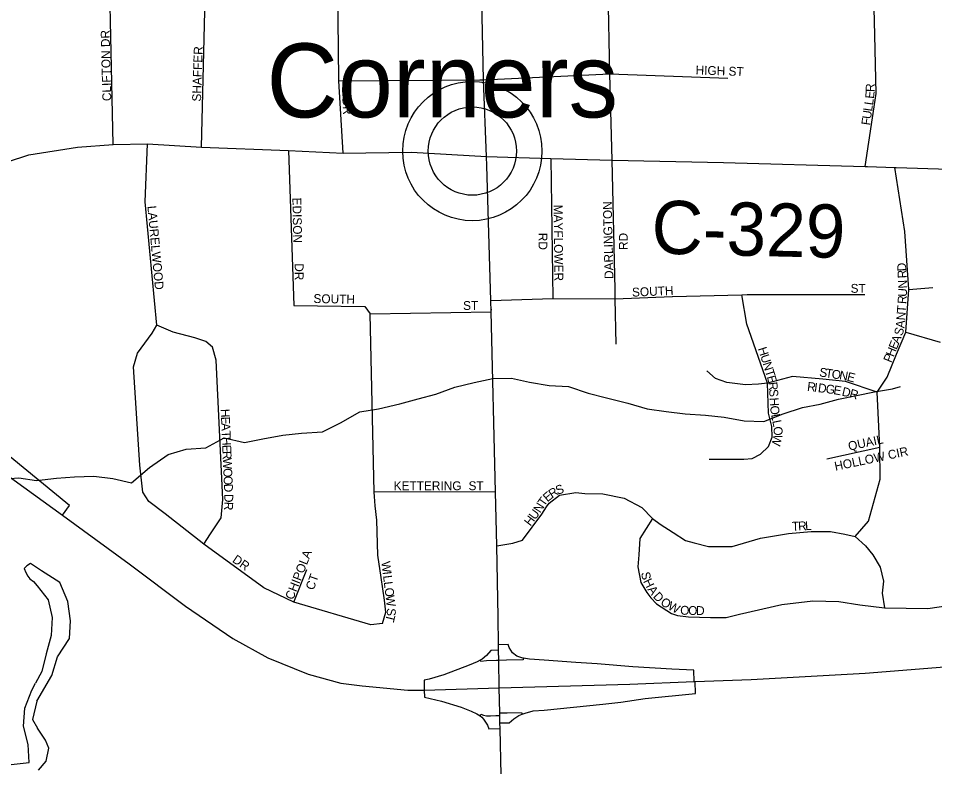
# Model space of a CAD drawing. Extents: x -37878.7 to -37844.7, y -19791.4 to -19769.4.
# Drawn here: x -37872 to -37871.021, y -19772.25 to -19771.451 of the extents above; entities that cross this region are included whole.
import ezdxf

# ---------------------------------------------------------------- set-up
doc = ezdxf.new("R2010")
doc.units = 0
for name, color, linetype in [('Default', 7, 'Continuous'), ('GM_X_County_Road', 7, 'Continuous'), ('GM_X_County_Road_Text', 7, 'Continuous'), ('GM_X_Interchange_Ramps', 7, 'Continuous'), ('GM_X_Major_River', 7, 'Continuous'), ('GM_X_Minor_River', 7, 'Continuous'), ('GM_X_State_Route', 7, 'Continuous'), ('GM_X_Township_Subdivision', 7, 'Continuous'), ('GM_X_Township_Subdivision_Text', 7, 'Continuous'), ('GM_X_Unincorporated', 7, 'Continuous'), ('GM_X_Unincorporated_Text', 7, 'Continuous')]:
    doc.layers.add(name, color=color, linetype=linetype)

msp = doc.modelspace()

# ---------------------------------------------------------------- linework, layer by layer
at = {"layer": 'Default'}
msp.add_line((-37871.51509, -19771.59241), (-37871.51509, -19771.59241), dxfattribs=at)
at = {"layer": 'GM_X_County_Road'}
for points in [[(-37872.01194, -19771.60377), (-37871.98912, -19771.59647), (-37871.93708, -19771.58825), (-37871.89901, -19771.58554), (-37871.86222, -19771.5846), (-37871.80471, -19771.58825), (-37871.71159, -19771.5919), (-37871.65316, -19771.59475), (-37871.57995, -19771.5934), (-37871.5, -19771.5981)], [(-37871.5, -19771.5981), (-37871.43129, -19771.60021), (-37871.36549, -19771.60206), (-37871.24669, -19771.60448), (-37871.09516, -19771.60885), (-37871.09272, -19771.60893), (-37871.0635, -19771.61001), (-37871.0623, -19771.61005), (-37871.00565, -19771.61165), (-37870.87873, -19771.6193), (-37870.79481, -19771.62682), (-37870.72767, -19771.63842), (-37870.70537, -19771.63741), (-37870.64056, -19771.65448), (-37870.56949, -19771.66605), (-37870.54222, -19771.67142), (-37870.49264, -19771.67596), (-37870.46113, -19771.67843), (-37870.24766, -19771.67679), (-37870.15647, -19771.6775), (-37870.10637, -19771.67103), (-37870.10594, -19771.67098)]]:
    msp.add_lwpolyline(points, dxfattribs=at)
at = {"layer": 'GM_X_Interchange_Ramps'}
for points in [[(-37871.95293, -19771.98122), (-37871.9456, -19771.97085), (-37872.07273, -19771.86712), (-37872.11453, -19771.83301), (-37872.28317, -19771.68716), (-37872.32336, -19771.65194), (-37872.49325, -19771.50307), (-37872.55567, -19771.44933), (-37872.57935, -19771.42714), (-37872.5973, -19771.40635), (-37872.61706, -19771.38265), (-37872.63797, -19771.35455), (-37872.67804, -19771.36574)], [(-37871.27805, -19772.15898), (-37871.27852, -19772.1469), (-37871.30204, -19772.14589), (-37871.34359, -19772.14315), (-37871.38156, -19772.13995), (-37871.40455, -19772.1385), (-37871.43829, -19772.13611), (-37871.45411, -19772.13522), (-37871.46054, -19772.13412), (-37871.46108, -19772.13402), (-37871.46742, -19772.13198), (-37871.4721, -19772.12823), (-37871.47574, -19772.12279), (-37871.47687, -19772.11959), (-37871.48711, -19772.11987)], [(-37871.48703, -19772.12549), (-37871.49542, -19772.12572), (-37871.49985, -19772.13099), (-37871.50469, -19772.13499), (-37871.50682, -19772.13619), (-37871.50996, -19772.13795), (-37871.51839, -19772.14132), (-37871.54558, -19772.15186), (-37871.56118, -19772.1565), (-37871.56665, -19772.15739), (-37871.56644, -19772.16804)], [(-37871.48685, -19772.13633), (-37871.4893, -19772.1364), (-37871.50006, -19772.13689), (-37871.50596, -19772.13773), (-37871.50682, -19772.13619)], [(-37871.46054, -19772.13412), (-37871.46085, -19772.13592), (-37871.47855, -19772.13611), (-37871.48685, -19772.13633)], [(-37871.48554, -19772.20324), (-37871.47569, -19772.203), (-37871.47077, -19772.19866), (-37871.4655, -19772.19508), (-37871.46195, -19772.19386), (-37871.45875, -19772.19276), (-37871.45011, -19772.19044), (-37871.43831, -19772.1896), (-37871.37572, -19772.18327), (-37871.35632, -19772.18096), (-37871.3304, -19772.17716), (-37871.27657, -19772.17162), (-37871.27707, -19772.15895)], [(-37871.56644, -19772.16804), (-37871.56631, -19772.17554), (-37871.54793, -19772.17993), (-37871.52686, -19772.18646), (-37871.51632, -19772.19068), (-37871.5102, -19772.19347), (-37871.50681, -19772.19548), (-37871.50485, -19772.19715), (-37871.50304, -19772.19911), (-37871.49903, -19772.20544), (-37871.49745, -19772.20941), (-37871.4854, -19772.20912)], [(-37871.50681, -19772.19548), (-37871.50597, -19772.19397), (-37871.50305, -19772.19507), (-37871.50007, -19772.19565), (-37871.49558, -19772.19557), (-37871.49005, -19772.19533), (-37871.48572, -19772.19524)], [(-37871.48578, -19772.19253), (-37871.47772, -19772.19234), (-37871.46255, -19772.19213), (-37871.46195, -19772.19386)]]:
    msp.add_lwpolyline(points, dxfattribs=at)
at = {"layer": 'GM_X_Major_River'}
for p, q in [((-37871.99116, -19772.03551), (-37871.99413, -19772.03814)), ((-37871.99413, -19772.03814), (-37871.99232, -19772.04234)), ((-37871.99232, -19772.04234), (-37871.99018, -19772.04637)), ((-37871.98721, -19772.03289), (-37871.99116, -19772.03551)), ((-37871.97995, -19772.03806), (-37871.98721, -19772.03289)), ((-37871.99018, -19772.04637), (-37871.98789, -19772.04934)), ((-37871.98789, -19772.04934), (-37871.98421, -19772.05201)), ((-37871.98421, -19772.05201), (-37871.98013, -19772.05691))]:
    msp.add_line(p, q, dxfattribs=at)
for points in [[(-37871.98068, -19772.18008), (-37871.9644, -19772.15246), (-37871.95859, -19772.13274), (-37871.94559, -19772.11305), (-37871.94472, -19772.09406), (-37871.94724, -19772.07354), (-37871.95582, -19772.05336), (-37871.97543, -19772.04074), (-37871.97995, -19772.03806)], [(-37871.98013, -19772.05691), (-37871.96843, -19772.07154), (-37871.96401, -19772.09055), (-37871.96526, -19772.10991), (-37871.97069, -19772.12926), (-37871.97535, -19772.14823), (-37871.98184, -19772.16074)], [(-37872.00807, -19772.24748), (-37871.98879, -19772.24555), (-37871.98995, -19772.22621), (-37871.9949, -19772.20658), (-37871.99341, -19772.18756), (-37871.98586, -19772.16804), (-37871.98184, -19772.16074)], [(-37871.98068, -19772.18008), (-37871.9852, -19772.19954), (-37871.9797, -19772.20891)], [(-37871.97877, -19772.25369), (-37871.97052, -19772.24397), (-37871.96754, -19772.23031), (-37871.97127, -19772.22156), (-37871.9797, -19772.20891)]]:
    msp.add_lwpolyline(points, dxfattribs=at)
at = {"layer": 'GM_X_Minor_River'}
for points in [[(-37871.98087, -19771.94423), (-37871.95965, -19771.94167), (-37871.94033, -19771.94024), (-37871.9195, -19771.93958), (-37871.89945, -19771.94196), (-37871.87941, -19771.94661), (-37871.86, -19771.93037), (-37871.84023, -19771.91641), (-37871.82088, -19771.9108), (-37871.80005, -19771.90938), (-37871.78029, -19771.89884), (-37871.75874, -19771.9035), (-37871.73903, -19771.89979), (-37871.7178, -19771.89572), (-37871.69772, -19771.89353), (-37871.67537, -19771.89212), (-37871.656, -19771.88272), (-37871.63548, -19771.87104), (-37871.61539, -19771.86772), (-37871.59264, -19771.86251), (-37871.57292, -19771.8569), (-37871.55396, -19771.85205), (-37871.53384, -19771.84455), (-37871.51299, -19771.83971), (-37871.49327, -19771.83525), (-37871.4732, -19771.83496), (-37871.45392, -19771.83923), (-37871.43312, -19771.84275), (-37871.4123, -19771.84399), (-37871.39114, -19771.85093), (-37871.37187, -19771.85596), (-37871.34881, -19771.86176), (-37871.3284, -19771.86756), (-37871.30797, -19771.87069), (-37871.28754, -19771.87307), (-37871.26597, -19771.87431), (-37871.24592, -19771.87669), (-37871.22474, -19771.88058), (-37871.20354, -19771.88107), (-37871.18305, -19771.87319), (-37871.16218, -19771.86645), (-37871.14322, -19771.86274), (-37871.12388, -19771.85751), (-37871.10455, -19771.85343), (-37871.08521, -19771.84972), (-37871.06588, -19771.8464), (-37871.05754, -19771.84377)], [(-37872.11221, -19771.98155), (-37872.09846, -19771.96354), (-37872.07821, -19771.95324), (-37872.05787, -19771.94787), (-37872.03828, -19771.94252), (-37872.01895, -19771.94286), (-37871.99966, -19771.94131), (-37871.98087, -19771.94423)]]:
    msp.add_lwpolyline(points, dxfattribs=at)
at = {"layer": 'GM_X_State_Route'}
for points in [[(-37871.4997, -19771.60813), (-37871.5, -19771.5981), (-37871.50303, -19771.51628), (-37871.50868, -19771.26212), (-37871.50889, -19771.23369), (-37871.51143, -19771.19794)], [(-37871.48915, -19771.99944), (-37871.49022, -19771.95652), (-37871.49513, -19771.76418), (-37871.49544, -19771.75192), (-37871.4997, -19771.60813)], [(-37872.0257, -19771.92896), (-37871.95293, -19771.98122), (-37871.88179, -19772.03336), (-37871.8216, -19772.07836), (-37871.77112, -19772.11308), (-37871.73362, -19772.13376), (-37871.69058, -19772.15118), (-37871.65576, -19772.16067), (-37871.63297, -19772.16353), (-37871.58392, -19772.16827), (-37871.56644, -19772.16804), (-37871.48639, -19772.16575)], [(-37871.48759, -19772.08976), (-37871.48879, -19772.01391), (-37871.48915, -19771.99944)], [(-37871.48639, -19772.16575), (-37871.48685, -19772.13633), (-37871.48703, -19772.12549), (-37871.48711, -19772.11987), (-37871.48759, -19772.08976)], [(-37871.21698, -19772.15663), (-37871.20426, -19772.15614), (-37871.09537, -19772.14992), (-37870.95701, -19772.13911)], [(-37871.48639, -19772.16575), (-37871.34662, -19772.16163), (-37871.27805, -19772.15898), (-37871.27707, -19772.15895), (-37871.21698, -19772.15663)], [(-37871.48426, -19772.25914), (-37871.4854, -19772.20912), (-37871.48554, -19772.20324), (-37871.48572, -19772.19524), (-37871.48578, -19772.19253), (-37871.48639, -19772.16575)]]:
    msp.add_lwpolyline(points, dxfattribs=at)
at = {"layer": 'GM_X_Township_Subdivision'}
for points in [[(-37871.89901, -19771.58554), (-37871.9049, -19771.30525), (-37871.90853, -19771.16537), (-37871.91106, -19771.02247), (-37871.91243, -19770.98276)], [(-37871.80471, -19771.58825), (-37871.79763, -19771.31186), (-37871.79517, -19771.23148)], [(-37871.65771, -19771.51587), (-37871.6591, -19771.38809), (-37871.66274, -19771.24545), (-37871.66071, -19771.2397)], [(-37871.09516, -19771.60885), (-37871.08339, -19771.53105), (-37871.08487, -19771.46857), (-37871.09051, -19771.23985)], [(-37871.36254, -19771.7401), (-37871.36549, -19771.60206), (-37871.36813, -19771.50983), (-37871.36993, -19771.41987), (-37871.37042, -19771.39232), (-37871.37042, -19771.38354), (-37871.3714, -19771.37525), (-37871.3714, -19771.36989), (-37871.3714, -19771.35794), (-37871.37154, -19771.34903)], [(-37871.50301, -19771.51628), (-37871.36813, -19771.50983), (-37871.24221, -19771.51454)], [(-37871.65316, -19771.59475), (-37871.65769, -19771.51731), (-37871.65771, -19771.51587)], [(-37871.65769, -19771.51731), (-37871.50714, -19771.5163), (-37871.50303, -19771.51628), (-37871.50301, -19771.51628)], [(-37871.61126, -19772.09697), (-37871.62368, -19772.09841), (-37871.7058, -19772.07406), (-37871.73779, -19772.05878), (-37871.80205, -19772.01216), (-37871.84331, -19771.98), (-37871.86098, -19771.96663), (-37871.86719, -19771.9566), (-37871.87053, -19771.92795), (-37871.87721, -19771.82291), (-37871.87292, -19771.80811), (-37871.85743, -19771.78685), (-37871.85239, -19771.77851), (-37871.86474, -19771.64678), (-37871.86222, -19771.5846)], [(-37871.71159, -19771.5919), (-37871.7058, -19771.7575)], [(-37871.43129, -19771.60021), (-37871.42914, -19771.74979)], [(-37871.10587, -19772.00399), (-37871.09155, -19771.98784), (-37871.07915, -19771.94271), (-37871.07964, -19771.90848), (-37871.08235, -19771.84992), (-37871.07167, -19771.8339), (-37871.06165, -19771.8092), (-37871.05164, -19771.78584), (-37871.0487, -19771.7402), (-37871.05297, -19771.67835), (-37871.0635, -19771.61001)], [(-37871.0487, -19771.7402), (-37871.02305, -19771.73803)], [(-37871.49544, -19771.75192), (-37871.42914, -19771.74979), (-37871.36232, -19771.7504), (-37871.30143, -19771.74781), (-37871.30128, -19771.7478)], [(-37871.36129, -19771.79877), (-37871.36232, -19771.7504), (-37871.36254, -19771.7401)], [(-37871.30128, -19771.7478), (-37871.22722, -19771.74578), (-37871.22132, -19771.74577)], [(-37871.26193, -19771.92136), (-37871.22485, -19771.92143), (-37871.21586, -19771.92068), (-37871.20719, -19771.91601), (-37871.19853, -19771.908), (-37871.19457, -19771.89785), (-37871.19488, -19771.88643), (-37871.1985, -19771.87239), (-37871.19974, -19771.84047), (-37871.22187, -19771.77715), (-37871.22722, -19771.74578)], [(-37871.22132, -19771.74577), (-37871.09563, -19771.74567)], [(-37871.7058, -19771.7575), (-37871.62989, -19771.75846), (-37871.62416, -19771.76609), (-37871.49513, -19771.76418), (-37871.49449, -19771.7611)], [(-37871.61955, -19771.9615), (-37871.61986, -19771.95674), (-37871.62416, -19771.76609)], [(-37871.80205, -19772.01216), (-37871.7951, -19772.00122), (-37871.78363, -19771.98429), (-37871.78172, -19771.96472), (-37871.78888, -19771.81575), (-37871.7927, -19771.8019), (-37871.79986, -19771.7957), (-37871.8118, -19771.79188), (-37871.83472, -19771.78567), (-37871.85239, -19771.77851)], [(-37871.05164, -19771.78584), (-37871.01516, -19771.79639)], [(-37871.08235, -19771.84992), (-37871.11639, -19771.83857), (-37871.14043, -19771.8359), (-37871.17308, -19771.83312), (-37871.19974, -19771.84047), (-37871.20919, -19771.84124), (-37871.22321, -19771.84191), (-37871.24294, -19771.83942), (-37871.25525, -19771.83523), (-37871.2646, -19771.82722)], [(-37871.1363, -19771.92126), (-37871.07964, -19771.90848)], [(-37871.49022, -19771.95652), (-37871.61986, -19771.95674)], [(-37871.61126, -19772.09697), (-37871.60745, -19772.08504), (-37871.60888, -19772.07215), (-37871.6127, -19772.0478), (-37871.61604, -19772.02392), (-37871.617, -19771.98668), (-37871.61891, -19771.9714), (-37871.61955, -19771.9615)], [(-37871.48879, -19772.01391), (-37871.4717, -19772.0113), (-37871.46142, -19772.00797), (-37871.44069, -19771.98019), (-37871.43594, -19771.97228), (-37871.43299, -19771.9684), (-37871.42201, -19771.95993), (-37871.4046, -19771.95708), (-37871.39479, -19771.95803), (-37871.37575, -19771.95858), (-37871.35294, -19771.96304), (-37871.33409, -19771.97296), (-37871.32268, -19771.98487), (-37871.31425, -19771.99082), (-37871.30036, -19771.99975), (-37871.28746, -19772.00818), (-37871.27804, -19772.01066), (-37871.26266, -19772.01463), (-37871.23737, -19772.01463), (-37871.20711, -19772.0057), (-37871.17736, -19772.00074), (-37871.15305, -19771.99875), (-37871.13222, -19771.99875), (-37871.11684, -19772.00173), (-37871.10587, -19772.00399), (-37871.09502, -19772.01413), (-37871.08708, -19772.02355), (-37871.07915, -19772.03695), (-37871.07568, -19772.05182), (-37871.07716, -19772.06472), (-37871.07468, -19772.0801)], [(-37871.32268, -19771.98487), (-37871.33607, -19772.0062), (-37871.33707, -19772.02355), (-37871.33806, -19772.03645), (-37871.33508, -19772.05331), (-37871.32864, -19772.06373), (-37871.32417, -19772.06968), (-37871.31821, -19772.07613), (-37871.3021, -19772.0863), (-37871.2959, -19772.08853), (-37871.28399, -19772.09002), (-37871.26068, -19772.09052), (-37871.24382, -19772.09052), (-37871.22943, -19772.08704), (-37871.1843, -19772.07662), (-37871.15107, -19772.07266), (-37871.12329, -19772.07365), (-37871.10097, -19772.07712), (-37871.07468, -19772.0801), (-37871.02813, -19772.08085), (-37870.99679, -19772.07619), (-37870.8562, -19772.07026)], [(-37871.7058, -19772.07406), (-37871.69181, -19772.03918)]]:
    msp.add_lwpolyline(points, dxfattribs=at)
at = {"layer": 'GM_X_Unincorporated'}
for radius in [0.0744, 0.04716]:
    msp.add_circle((-37871.51509, -19771.59241), radius, dxfattribs=at)

# ---------------------------------------------------------------- texts
at = {"layer": 'GM_X_County_Road_Text'}
msp.add_text('C-329', height=0.056818, rotation=358.6232, dxfattribs=at).set_placement((-37871.32405, -19771.70174))
at = {"layer": 'GM_X_Township_Subdivision_Text'}
for s, rotation, p in [('CLIFTON DR', 91.41637, (-37871.90095, -19771.53893)), ('SHAFFER', 88.12317, (-37871.80512, -19771.53966)), ('HIGH ST', 357.87808, (-37871.27661, -19771.51044)), ('R', 89.15768, (-37871.08523, -19771.5293)), ('E', 84.02652, (-37871.08598, -19771.53684)), ('DR', 273.01099, (-37871.65406, -19771.53546)), ('L', 81.72115, (-37871.08699, -19771.54385)), ('U', 81.7276, (-37871.08915, -19771.55869)), ('L', 81.73869, (-37871.08795, -19771.55044)), ('F', 81.72115, (-37871.09011, -19771.56529)), ('EDISON', 271.12697, (-37871.70739, -19771.64218)), ('MAYFLOWER', 270.63625, (-37871.42822, -19771.6497)), ('DARLINGTON', 91.25837, (-37871.36429, -19771.72892)), ('LAURELWOOD', 275.24651, (-37871.86239, -19771.65122)), ('RD', 270, (-37871.44434, -19771.67972)), ('RD', 90, (-37871.34901, -19771.69805)), ('DR', 270, (-37871.70489, -19771.71222)), ('D', 93.17075, (-37871.05124, -19771.72054)), ('R', 93.18321, (-37871.05083, -19771.72803)), ('SOUTH', 2.48831, (-37871.34425, -19771.74793)), ('ST', 0.00001, (-37871.11084, -19771.74376)), ('N', 92.42184, (-37871.05033, -19771.73899)), ('SOUTH', 358.75525, (-37871.68497, -19771.7546)), ('R', 85.81921, (-37871.0513, -19771.75599)), ('U', 87.20065, (-37871.05074, -19771.74826)), ('ST', 0.00001, (-37871.52501, -19771.7621)), ('T', 85.81607, (-37871.05197, -19771.76513)), ('N', 85.8265, (-37871.05257, -19771.77344)), ('A', 85.01468, (-37871.05331, -19771.78189)), ('S', 72.46075, (-37871.05576, -19771.79046)), ('E', 67.605, (-37871.06178, -19771.80516)), ('A', 67.59801, (-37871.05924, -19771.79899)), ('H', 287.56068, (-37871.20998, -19771.80334)), ('H', 67.61182, (-37871.06495, -19771.81286)), ('U', 287.53983, (-37871.20746, -19771.81128)), ('P', 67.605, (-37871.06749, -19771.81902)), ('N', 287.56182, (-37871.20495, -19771.81923)), ('T', 287.56671, (-37871.20244, -19771.82718)), ('S', 351.56652, (-37871.14475, -19771.83295)), ('T', 351.57086, (-37871.13816, -19771.83393)), ('O', 351.5792, (-37871.13156, -19771.83491)), ('E', 285.48756, (-37871.20045, -19771.83345)), ('N', 350.03823, (-37871.12339, -19771.83612)), ('E', 345.77161, (-37871.11536, -19771.83752)), ('R', 276.44881, (-37871.19874, -19771.83948)), ('R', 352.71833, (-37871.15768, -19771.84827)), ('I', 352.70147, (-37871.15024, -19771.84922)), ('D', 352.72295, (-37871.1461, -19771.84975)), ('G', 352.19447, (-37871.13786, -19771.8508)), ('E', 350.33552, (-37871.12969, -19771.85192)), ('D', 347.01358, (-37871.1208, -19771.8535)), ('R', 343.83111, (-37871.11282, -19771.85534)), ('S', 273.25257, (-37871.19791, -19771.8468)), ('H', 273.1271, (-37871.1974, -19771.85594)), ('O', 275.6596, (-37871.19691, -19771.86472)), ('H', 272.44874, (-37871.78406, -19771.86797)), ('L', 281.72768, (-37871.19592, -19771.87409)), ('E', 272.44691, (-37871.7837, -19771.8763)), ('A', 272.44874, (-37871.78342, -19771.88296)), ('L', 280.9134, (-37871.19457, -19771.88059)), ('T', 272.44691, (-37871.78306, -19771.89128)), ('O', 273.80608, (-37871.19335, -19771.88683)), ('H', 272.44874, (-37871.78277, -19771.89794)), ('W', 256.95875, (-37871.19274, -19771.89441)), ('QUAIL', 12.09582, (-37871.11235, -19771.91242)), ('E', 272.44691, (-37871.78242, -19771.90627)), ('R', 272.4537, (-37871.78213, -19771.91293)), ('HOLLOW CIR', 11.95648, (-37871.127, -19771.93391)), ('W', 272.4556, (-37871.78181, -19771.92042)), ('O', 272.44874, (-37871.78135, -19771.93124)), ('O', 272.4391, (-37871.78099, -19771.93957)), ('D', 272.4443, (-37871.78063, -19771.94789)), ('KETTERING', 0.00001, (-37871.59917, -19771.9546)), ('ST', 0.00001, (-37871.51917, -19771.9546)), ('R', 32.84467, (-37871.42993, -19771.96355)), ('S', 20.82467, (-37871.42409, -19771.95971)), ('D', 270.65566, (-37871.78017, -19771.95864)), ('T', 54.96097, (-37871.43815, -19771.97265)), ('E', 40.24277, (-37871.43476, -19771.96766)), ('R', 267.13334, (-37871.78007, -19771.96682)), ('N', 57.62365, (-37871.44255, -19771.97959)), ('H', 52.68859, (-37871.45309, -19771.99363)), ('U', 53.30399, (-37871.44797, -19771.98691)), ('T', 2.36433, (-37871.17342, -19771.99793)), ('R', 2.37116, (-37871.16675, -19771.99766)), ('L', 2.14486, (-37871.15927, -19771.99735)), ('CHIPOLA', 68.55274, (-37871.70667, -19772.0724)), ('DR', 325.4967, (-37871.77233, -19772.03075)), ('W', 277.02806, (-37871.6124, -19772.03117)), ('I', 277.01117, (-37871.61108, -19772.04192)), ('S', 281.85912, (-37871.3349, -19772.04286)), ('CT', 70.55862, (-37871.68466, -19772.06204)), ('L', 277.04164, (-37871.61057, -19772.04606)), ('H', 296.0009, (-37871.3327, -19772.05179)), ('L', 277.03862, (-37871.60975, -19772.05267)), ('O', 277.01117, (-37871.60894, -19772.05929)), ('A', 305.16478, (-37871.32821, -19772.0607)), ('W', 277.03511, (-37871.60792, -19772.06757)), ('D', 312.38787, (-37871.32259, -19772.06853)), ('O', 327.82829, (-37871.31484, -19772.07647)), ('S', 268.22373, (-37871.6063, -19772.08042)), ('W', 333.09266, (-37871.30696, -19772.08137)), ('O', 357.13864, (-37871.29314, -19772.08738)), ('O', 359.2045, (-37871.28444, -19772.08781)), ('D', 359.97035, (-37871.27597, -19772.08793)), ('T', 256.17909, (-37871.60644, -19772.08656))]:
    msp.add_text(s, height=0.00947, rotation=rotation, dxfattribs=at).set_placement(p)
at = {"layer": 'GM_X_Unincorporated_Text'}
msp.add_text('Corners', height=0.078977, rotation=0.00001, dxfattribs=at).set_placement((-37871.73501, -19771.55643))

doc.saveas('drawing.dxf')
